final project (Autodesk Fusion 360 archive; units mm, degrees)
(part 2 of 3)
description: Part Number
part number: Ceramic
part number: Contacts
part number: Contacts (Mirror #1)
part number: Overcoat
part number: Resistor-1206
part number: SOT-223
part number: FINALALI 1.3.1
part number: FINALALI 1.3.2
part number: Header_SMD_01x02_P2.54mm_Horizontal_Male
base_feature "Base Feature1"
base_feature "Base Feature1"
base_feature "Base Feature1"
base_feature "Base Feature1"
base_feature "Base Feature1"
base_feature "Base Feature1"
base_feature "Base Feature1"
base_feature "Base Feature1"
base_feature "Base Feature1"
base_feature "Base Feature1"
base_feature "Base Feature1"
base_feature "Base Feature1"
base_feature "Base Feature1"
base_feature "Base Feature1"
base_feature "Base Feature1"
base_feature "Base Feature1"
base_feature "Base Feature1"
base_feature "Base Feature1"
base_feature "Base Feature1"
base_feature "Base Feature1"
base_feature "Base Feature1"
base_feature "Base Feature1"
base_feature "Base Feature1"
base_feature "Base Feature1"
base_feature "Base Feature1"
base_feature "Base Feature1"
base_feature "Base Feature1"
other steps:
create_component "CreateComponent1"
create_component "CreateComponent1"
create_component "CreateComponent2"
create_component "CreateComponent3"
create_component "CreateComponent4"
create_component "CreateComponent2"
create_component "CreateComponent3"
create_component "CreateComponent1"
create_component "CreateComponent2"
create_component "CreateComponent4"
create_component "CreateComponent1"
create_component "CreateComponent2"
create_component "CreateComponent3"
create_component "CreateComponent5"
create_component "CreateComponent6"
create_component "CreateComponent1"
create_component "CreateComponent2"
create_component "CreateComponent3"
create_component "CreateComponent4"
create_component "CreateComponent7"
create_component "CreateComponent1"
create_component "CreateComponent8"
create_component "CreateComponent1"
create_component "CreateComponent2"
create_component "CreateComponent9"
create_component "CreateComponent1"
create_component "CreateComponent2"
create_component "CreateComponent1"
create_component "CreateComponent2"
create_component "CreateComponent3"
create_component "CreateComponent4"
create_component "CreateComponent3"
create_component "CreateComponent4"
create_component "CreateComponent10"
create_component "CreateComponent11"

design "Enclosure" references "PCB TEST", "FINAL ALI", "FINALALI"
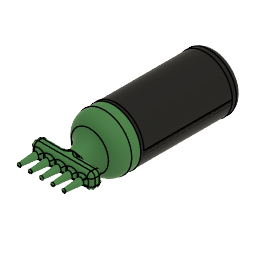
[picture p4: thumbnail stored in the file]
parameter "CLEARANCE" = 0.3
parameter "circle_1" = 54
parameter "fillet" = 10
parameter "d265" = 3
parameter "d322" = 7
sketch "Sketch1" plane through (0, 0, 0) normal (1, 0, 0) x axis (0, 1, 0)
  line L1 (-56, 12.5) -> (-56, 0)
  line L2 (-44, 12.5) -> (-56, 12.5)
  line L3 (-44, 27) -> (-44, 12.5)
  line L4 (56, 27) -> (-44, 27)
  line L5 (56, 0) -> (56, 27)
  line L6 (-56, 0) -> (56, 0)
  line L7 (46, 17) -> (46, 27)
  line L8 (56, 17) -> (46, 17)
  line L9 (-56, 12.5) -> (-44, 12.5)
  line L10 (-56, 27) -> (-56, 12.5)
  line L11 (-44, 27) -> (-56, 27)
  line L12 (-44, 12.5) -> (-44, 27)
  line L13 (55, 16.9) -> (55, 17)
  line L14 (56, 16.9) -> (55, 16.9)
  point P1 (0, 0)
  point P8 (46, 27)
  point P10 (56, 17)
  point P14 (55, 17)
  point P16 (56, 16.9)
  point P6 (56, 27)
  point P7 (56, 0)
  point P2 (-56, 0)
  point P3 (-56, 12.5)
  point P5 (-44, 27)
  point P9 (46, 17)
  point P15 (55, 16.9)
  vertical L1
  perpendicular L1 L2
  perpendicular L2 L3
  perpendicular L3 L4
  perpendicular L4 L5
  perpendicular L1 L6
  midpoint P1 L6
  coincident L4 P8
  perpendicular L4 L7
  coincident L5 P10
  perpendicular L5 L8
  horizontal L9
  vertical L10
  horizontal L11
  vertical L12
  collinear L1 L10
  collinear L4 L11
  coincident L8 P14
  perpendicular L8 L13
  coincident L5 P16
  perpendicular L5 L14
  dimension "d1" distance P6 P7 = 27
  dimension "d2" distance P2 P3 = 12.5 (= "( 25 / 2 ) * 1 mm")
  dimension "d3" distance L1 L3 = 12
  dimension "d4" distance P5 P6 = 100
  dimension "d5" distance P9 P10 = 10
  dimension "d79" distance P15 P16 = 1
  dimension "d80" distance P14 P15 = 0.1
  dimension "d173" distance P7 L8 = 17
revolve "Revolve1" sketch "Sketch1" AlongAngle 360
revolve "Revolve2" sketch "Sketch1" AlongAngle 360 bodies "back cover"
shell "Shell1" innerThickness 3
split "Split1"
split "Split2"
split "Split3" bodies "top cover"
combine "Combine2"
sketch "Sketch2" plane through (0, 46, 0) normal (0, 1, 0) x axis (-1, 0, 0)
  line L1 (-27, 0) -> (-24, 0)
  line L2 (24, 0) -> (27, 0)
  line L3 (0, -27) -> (0, 24)
  line L4 (-24.955, -1.5) -> (-25.9052, -2.2186)
  line L5 (-24.5605, -4.6669) -> (-25.658, -4.2033)
  line L6 (0, 0) -> (-26.793, -3.3369)
  line L7 (24.955, -1.5) -> (25.9052, -2.2186)
  line L8 (24.5605, -4.6669) -> (25.658, -4.2033)
  line L9 (-23.5661, -4.543) -> (-24.5605, -4.6669)
  line L10 (23.5661, -4.543) -> (24.5605, -4.6669)
  arc A1 centre (0, 0) radius 24 clockwise from (-24, 0) to (24, 0)
  arc A2 centre (0, 0) radius 27 clockwise from (27, 0) to (-27, 0)
  circle C1 centre (0, 0) radius 17
  circle C2 centre (0, 0) radius 24
  circle C3 centre (0, 0) radius 23.5
  circle C4 centre (0, 0) radius 25
  circle C5 centre (0, 0) radius 26
  point P7 (0, 24)
  point P8 (0, -27)
  point P3 (-24, 0)
  point P13 (-25.9052, -2.2186)
  point P14 (-24.955, -1.5)
  point P15 (-25.658, -4.2033)
  point P16 (-24.5605, -4.6669)
  point P17 (-26.793, -3.3369)
  point P4 (0, 0)
  point P18 (0, 0)
  point P19 (25.9052, -2.2186)
  point P20 (24.955, -1.5)
  point P21 (25.658, -4.2033)
  point P22 (24.5605, -4.6669)
  point P23 (-23.5661, -4.543)
  point P24 (24.5605, -4.6669)
  point P25 (23.5661, -4.543)
  midpoint A1 P7
  midpoint A2 P8
  concentric A1 C2
  coincident P3 C2
  concentric A1 C3
  concentric A1 C4
  concentric C4 C5
  coincident C5 P13
  coincident C4 P14
  coincident C5 P15
  coincident C4 P16
  coincident A2 P17
  coincident P4 P18
  symmetric L4 L5 L6
  symmetric L3 P13 P19
  symmetric L3 P14 P20
  symmetric L3 P15 P21
  symmetric L3 P16 P22
  coincident C2 P23
  parallel L6 L9
  symmetric L3 P16 P24
  symmetric L3 P23 P25
  dimension "d10" distance C2 C4 = 1
  dimension "d11" distance A2 C5 = 1
  dimension "d12" distance P13 P15 = 2
  dimension "d13" angle L5 L6 = 30
  dimension "d14" distance L1 P14 = 1.5
extrude "Extrude1" add sketch "Sketch2" profile of L1 L2 C2 C4 C5 L4 L5 L7 L8 L9 L10 to an object
extrude "Extrude2" add sketch "Sketch2" profile of A1 L1 L2 C2 C4 along normal blind 1.5
extrude "Extrude3" of existing geometry blind -1.5
combine "Combine3"
extrude "Extrude4" add sketch "Sketch2" profile of C2 C4 L9 L10 along normal blind 1.5
extrude "Extrude5" cut sketch "Sketch2" profile of A1 L1 L2 C2 C4 L9 L10 along normal blind 1.8
offset_faces "OffsetFaces1"
offset_faces "OffsetFaces2"
offset_faces "OffsetFaces3"
extrude "Extrude6" add sketch "Sketch2" profile of L1 L2 C2 C4 L9 L10 to an object
thread "Thread4" ThreadOffset 0 ThreadLength 10
combine "Combine4"
offset_faces "OffsetFaces12" distance -0.3
thread "Thread9" ThreadOffset 0 ThreadLength 10
sketch "Sketch10" plane through (0, -41, 0) normal (0, 1, 0) x axis (-1, 0, 0)
  line L1 (-26.2177, -2.0789) -> (-25.2636, -1.3573)
  line L2 (-24.6032, -4.9745) -> (-25.9267, -4.4154)
  line L3 (-23.5073, -4.838) -> (-24.6032, -4.9745)
  line L4 (25.1559, -4.741) -> (23.5661, -4.543)
  line L5 (25.9267, -4.4154) -> (25.1559, -4.741)
  line L6 (25.2636, -1.3573) -> (26.2177, -2.0789)
  line L7 (23.6981, -0.3) -> (25.2982, -0.3)
  line L8 (-25.2982, -0.3) -> (-23.6981, -0.3)
  line L9 (-1, 9.4472) -> (1, 9.4472)
  line L10 (-1, -9.4472) -> (-1, 9.4472)
  line L11 (1, -9.4472) -> (-1, -9.4472)
  line L12 (1, 9.4472) -> (1, -9.4472)
  line L13 (-1, -9.4472) -> (1, 9.4472)
  line L14 (1, -9.4472) -> (-1, 9.4472)
  circle C1 centre (0, 0) radius 9.5
  arc A1 centre (0, 0) radius 26.3 clockwise from (-25.9267, -4.4154) to (-26.2177, -2.0789)
  arc A2 centre (0, 0) radius 24 clockwise from (23.5661, -4.543) to (-23.5073, -4.838)
  arc A3 centre (0, 0) radius 26.3 clockwise from (26.2177, -2.0789) to (25.9267, -4.4154)
  arc A4 centre (0, 0) radius 25.3 clockwise from (25.2982, -0.3) to (25.2636, -1.3573)
  arc A5 centre (0, 0) radius 23.7 clockwise from (-23.6981, -0.3) to (23.6981, -0.3)
  arc A6 centre (0, 0) radius 25.3 clockwise from (-25.2636, -1.3573) to (-25.2982, -0.3)
  circle C2 centre (4.2, 0) radius 2.5
  circle C3 centre (4.2, 0) radius 1.25
  point P21 (0, 0)
  point P17 (1, 9.4472)
  point P2 (0, 0)
  point P19 (-1, -9.4472)
  point P20 (1, -9.4472)
  horizontal L9
  perpendicular L9 L10
  parallel L9 L11
  parallel L10 L12
  coincident L13 P21
  coincident L14 P21
  coincident C1 P17
  coincident P2 P21
  concentric C2 C3
  dimension "d106" distance P19 P20 = 2
  dimension "d111" diameter C2 = 5
  dimension "d117" diameter C3 = 2.5
extrude "Extrude14" add sketch "Sketch10" profile of C1 L9 L10 L11 L12 against normal blind 15
extrude "Extrude15" add sketch "Sketch10" profile of C1 L12 against normal blind 5
sketch "Sketch11" plane through (0, -41, 0) normal (0, 1, 0) x axis (-1, 0, 0)
  circle C1 centre (4.1977, -0.018) radius 1.25
  dimension "d114" diameter C1 = 2.5
extrude "Extrude17" cut sketch "Sketch11" against normal blind 15.8
mirror "Mirror1" mirrorStitchTolerance 0.1
sketch "Sketch12" plane through (0, -41, 0) normal (0, 1, 0) x axis (-1, 0, 0)
  line L1 (-24.6032, -4.9745) -> (-25.9267, -4.4154)
  line L2 (-23.5073, -4.838) -> (-24.6032, -4.9745)
  line L3 (25.1559, -4.741) -> (23.5661, -4.543)
  line L4 (25.9267, -4.4154) -> (25.1559, -4.741)
  line L5 (25.2636, -1.3573) -> (26.2177, -2.0789)
  line L6 (23.6981, -0.3) -> (25.2982, -0.3)
  line L7 (-25.2982, -0.3) -> (-23.6981, -0.3)
  line L8 (-26.2177, -2.0789) -> (-25.2636, -1.3573)
  circle C1 centre (4.1977, -0.018) radius 1.25
  circle C2 centre (-4.1977, -0.018) radius 1.25
  arc A1 centre (0, 0) radius 24 clockwise from (23.5661, -4.543) to (-23.5073, -4.838)
  arc A2 centre (0, 0) radius 26.3 clockwise from (26.2177, -2.0789) to (25.9267, -4.4154)
  arc A3 centre (0, 0) radius 25.3 clockwise from (25.2982, -0.3) to (25.2636, -1.3573)
  arc A4 centre (0, 0) radius 23.7 clockwise from (-23.6981, -0.3) to (23.6981, -0.3)
  arc A5 centre (0, 0) radius 25.3 clockwise from (-25.2636, -1.3573) to (-25.2982, -0.3)
  arc A6 centre (0, 0) radius 26.3 clockwise from (-25.9267, -4.4154) to (-26.2177, -2.0789)
  circle C3 centre (-4.1977, -0.018) radius 2.5
  concentric C2 C3
  dimension "d122" diameter C3 = 5
extrude "Extrude19" add sketch "Sketch12" profile of C2 C3 along normal blind 10
sketch "Sketch13" plane through (0, -41, 0) normal (0, 1, 0) x axis (-1, 0, 0)
  line L1 (-24.6032, -4.9745) -> (-25.9267, -4.4154)
  line L2 (-23.5073, -4.838) -> (-24.6032, -4.9745)
  line L3 (25.1559, -4.741) -> (23.5661, -4.543)
  line L4 (25.9267, -4.4154) -> (25.1559, -4.741)
  line L5 (25.2636, -1.3573) -> (26.2177, -2.0789)
  line L6 (23.6981, -0.3) -> (25.2982, -0.3)
  line L7 (-25.2982, -0.3) -> (-23.6981, -0.3)
  line L8 (-26.2177, -2.0789) -> (-25.2636, -1.3573)
  arc A1 centre (0, 0) radius 24 clockwise from (23.5661, -4.543) to (-23.5073, -4.838)
  arc A2 centre (0, 0) radius 26.3 clockwise from (26.2177, -2.0789) to (25.9267, -4.4154)
  arc A3 centre (0, 0) radius 25.3 clockwise from (25.2982, -0.3) to (25.2636, -1.3573)
  arc A4 centre (0, 0) radius 23.7 clockwise from (-23.6981, -0.3) to (23.6981, -0.3)
  arc A5 centre (0, 0) radius 25.3 clockwise from (-25.2636, -1.3573) to (-25.2982, -0.3)
  arc A6 centre (0, 0) radius 26.3 clockwise from (-25.9267, -4.4154) to (-26.2177, -2.0789)
  circle C1 centre (4.1977, -0.018) radius 1.25
  circle C2 centre (4.1977, -0.018) radius 2.5
  circle C3 centre (-4.1977, -0.018) radius 2.5
  concentric C1 C2
  dimension "d127" diameter C2 = 5
extrude "Extrude20" add sketch "Sketch13" profile of C1 C2 along normal blind 10
fillet "Fillet11" radius 3
sketch "Sketch14" plane through (0, 56, 0) normal (0, 1, 0) x axis (-1, 0, 0)
  line L1 (-10.15, 2.015) -> (10.15, 2.015)
  line L2 (-10.15, -2.015) -> (-10.15, 2.015)
  line L3 (10.15, -2.015) -> (-10.15, -2.015)
  line L4 (10.15, 2.015) -> (10.15, -2.015)
  line L5 (-10.15, -2.015) -> (10.15, 2.015)
  line L6 (10.15, -2.015) -> (-10.15, 2.015)
  circle C1 centre (0, 0) radius 16.9
  point P7 (0, 0)
  point P1 (0, 0)
  point P5 (-10.15, -2.015)
  point P6 (10.15, -2.015)
  point P4 (-10.15, 2.015)
  horizontal L1
  perpendicular L1 L2
  parallel L1 L3
  parallel L2 L4
  coincident L5 P7
  coincident L6 P7
  coincident P1 P7
  dimension "d134" distance P5 P6 = 20.3
  dimension "d135" distance P4 P5 = 4.03
extrude "Extrude21" cut sketch "Sketch14" profile of L1 L2 L3 L4 against normal blind 35
fillet "Fillet12" radius 2
chamfer "Chamfer4" distance 1
sketch "Sketch15" plane through (0, -44, 0) normal (0, -1, 0) x axis (1, 0, 0)
  curve K1 (4.9507, -9.5814) -> (7.7632, 9.8383)
  curve K2 (-3.6675, 11.9837) -> (-8.088, -7.1342)
  line L1 (0, 27) -> (0, 0)
  line L2 (0, -27) -> (0, 0)
  line L3 (1, -13.5) -> (-1, -13.5)
  line L4 (2, -23) -> (2, -14.5)
  line L5 (-1, -24) -> (1, -24)
  line L6 (-2, -14.5) -> (-2, -23)
  line L7 (2, -16) -> (-2, -16)
  line L8 (2, -22) -> (-2, -22)
  line L9 (1, -23) -> (-1, -23)
  line L10 (1, -14.5) -> (-1, -14.5)
  arc A1 centre (0, 0) radius 12.5324 clockwise from (-3.6675, 11.9837) to (7.7632, 9.8383)
  arc A2 centre (0, 0) radius 10.7848 clockwise from (4.9507, -9.5814) to (-8.088, -7.1342)
  circle C1 centre (0, 0) radius 27
  circle C2 centre (0, 0) radius 18
  circle C3 centre (0, 0) radius 20
  circle C4 centre (0, 0) radius 27
  circle C5 centre (0, 0) radius 16
  circle C6 centre (0, 0) radius 22
  arc A3 centre (-1, -14.5) radius 1 clockwise from (-2, -14.5) to (-1, -13.5)
  arc A4 centre (1, -14.5) radius 1 clockwise from (1, -13.5) to (2, -14.5)
  arc A5 centre (1, -23) radius 1 clockwise from (2, -23) to (1, -24)
  arc A6 centre (-1, -23) radius 1 clockwise from (-1, -24) to (-2, -23)
  circle C7 centre (0, -23) radius 0.45
  circle C8 centre (0, -14.5) radius 0.45
  point P1 (0, 0)
  point P7 (0, 0)
  point P8 (0, 0)
  point P12 (0, 0)
  point P13 (0, 27)
  point P14 (0, -27)
  point P15 (-2, -16)
  point P16 (2, -16)
  point P17 (-2, -22)
  point P18 (2, -22)
  point P30 (-1, -23)
  point P31 (-1, -23)
  point P27 (1, -23)
  point P32 (1, -23)
  point P33 (0, -23)
  point P21 (-1, -14.5)
  point P34 (-1, -14.5)
  point P24 (1, -14.5)
  point P35 (1, -14.5)
  point P36 (0, -14.5)
  coincident P1 P7
  coincident P1 P8
  concentric C2 C5
  coincident P7 P12
  coincident C4 P13
  vertical L1
  coincident C4 P14
  vertical L2
  horizontal L3
  vertical L4
  horizontal L5
  vertical L6
  symmetric L2 L4 L6
  coincident L6 P15
  coincident L4 P16
  perpendicular L4 L7
  coincident L6 P17
  coincident L4 P18
  perpendicular L4 L8
  tangent C5 L7
  tangent C6 L8
  tangent L3 A3
  tangent L6 A3
  tangent L3 A4
  tangent L4 A4
  equal A3 A4
  tangent L4 A5
  tangent L5 A5
  equal A3 A5
  tangent L5 A6
  tangent L6 A6
  equal A3 A6
  coincident P30 P31
  coincident P27 P32
  midpoint L9 P33
  coincident P21 P34
  coincident P24 P35
  midpoint L10 P36
  dimension "d151" distance C1 C6 = 5
  dimension "d152" distance C3 C6 = 2
  dimension "d153" distance C2 C3 = 2
  dimension "d154" distance C2 C5 = 2
  dimension "d176" distance L5 L8 = 2
  dimension "d177" distance L3 L7 = 2.5
  dimension "d178" distance L4 L6 = 4
  dimension "d179" radius A3 = 1
  dimension "d180" diameter C7 = 0.9
  dimension "d181" diameter C8 = 0.9
fillet "Fillet13" radius 6
chamfer "Chamfer5" distance 3
chamfer "Chamfer6" distance 3
fillet "Fillet14" radius 2
extrude "Extrude23" cut sketch "Sketch15" profile of C2 C3 C6 C5 L1 L3 L4 L5 L6 A3 A4 A5 A6 C7 C8 against normal blind 1.77 (magnitude of "-1.17 mm - 0.60 mm")
extrude "Extrude24" cut sketch "Sketch15" profile of C7 C8 against normal blind 6.7
fillet "Fillet16" radius 1
sketch "Sketch17" plane through (0, -42.23, 0) normal (0, -1, 0) x axis (1, 0, 0)
  line L1 (2, -14.5) -> (2, -14.6969)
  line L2 (-1, -13.5) -> (1, -13.5)
  line L3 (-2, -14.6969) -> (-2, -14.5)
  line L4 (-2, -23) -> (-2, -22.8035)
  line L5 (1, -24) -> (-1, -24)
  line L6 (2, -22.8035) -> (2, -23)
  circle C1 centre (0, -14.5) radius 0.45
  circle C2 centre (0, -23) radius 0.45
  arc A1 centre (1, -14.5) radius 1 clockwise from (1, -13.5) to (2, -14.5)
  arc A2 centre (-1, -14.5) radius 1 clockwise from (-2, -14.5) to (-1, -13.5)
  arc A3 centre (-3, -14.6969) radius 1 clockwise from (-2, -14.6969) to (-3.2, -15.6767)
  arc A4 centre (0, 0) radius 16 clockwise from (-3.2, -15.6767) to (3.2, -15.6767)
  arc A5 centre (3, -14.6969) radius 1 clockwise from (3.2, -15.6767) to (2, -14.6969)
  arc A6 centre (-1, -23) radius 1 clockwise from (-1, -24) to (-2, -23)
  arc A7 centre (1, -23) radius 1 clockwise from (2, -23) to (1, -24)
  arc A8 centre (3, -22.8035) radius 1 clockwise from (2, -22.8035) to (2.8696, -21.8121)
  arc A9 centre (0, 0) radius 22 clockwise from (-2.8696, -21.8121) to (2.8696, -21.8121)
  arc A10 centre (-3, -22.8035) radius 1 clockwise from (-2.8696, -21.8121) to (-2, -22.8035)
  circle C3 centre (0, 0) radius 18.1
  circle C4 centre (0, 0) radius 19.9
  concentric A4 C3
  concentric C3 C4
  dimension "d186" distance A4 C3 = 2.1
  dimension "d187" distance A9 C4 = 2.1
sketch "Sketch1" plane through (0, 0, 0) normal (0, 1, 0) x axis (1, 0, 0)
  line L1 (-20, -20) -> (20, -20)
  line L2 (-20, 20) -> (-20, -20)
  line L3 (20, 20) -> (-20, 20)
  line L4 (20, -20) -> (20, 20)
  line L5 (-20, 20) -> (20, -20)
  line L6 (20, 20) -> (-20, -20)
  point P6 (0, 0)
  point P1 (0, 0)
  point P4 (-20, 20)
  point P5 (20, 20)
  point P3 (-20, -20)
  horizontal L1
  perpendicular L1 L2
  parallel L1 L3
  parallel L2 L4
  coincident L5 P6
  coincident L6 P6
  coincident P1 P6
  dimension "d1_2" distance P4 P5 = 40
  dimension "d2_2" distance P3 P4 = 40
extrude "Extrude1" new body sketch "Sketch1" profile of L1 L2 L3 L4 distance 6 named "d3_2"
sketch "Sketch2" plane through (0, 0, 20) normal (0, 0, 1) x axis (-1, 0, 0)
  line L1 (-20, -6) -> (-20, 6)
  line L2 (20, -6) -> (-20, -6)
  line L3 (20, 6) -> (20, -6)
  line L4 (-20, 6) -> (20, 6)
  circle C1 centre (15, 0) radius 3.8143
  circle C2 centre (-15, 0) radius 3.6582
extrude "Extrude2" add sketch "Sketch2" profile of C1 C2 along normal blind 12 named "d5_2"
chamfer "Chamfer1" distance 1.5 named "d7_2"
component_insert "Component Insert20"
position "Position18"
sketch "Sketch33" plane through (0, 0, 0) normal (0, 1, 0) x axis (1, 0, 0)
  line L1 (25.9052, 2.2186) -> (24.955, 1.5)
  line L2 (24.5605, 4.6669) -> (25.658, 4.2033)
  line L3 (23.5661, 4.543) -> (24.5605, 4.6669)
  line L4 (-24.5605, 4.6669) -> (-23.5661, 4.543)
  line L5 (-25.658, 4.2033) -> (-24.5605, 4.6669)
  line L6 (-24.955, 1.5) -> (-25.9052, 2.2186)
  line L7 (-27, 0) -> (-25, 0)
  line L8 (25, 0) -> (27, 0)
  line L9 (26.9983, 0.3) -> (25.2982, 0.3)
  line L10 (-25.3, 0) -> (-27, 0)
  line L11 (-26.2177, 2.0789) -> (-25.2636, 1.3573)
  line L12 (-25.1559, 4.741) -> (-25.9267, 4.4154)
  line L13 (-23.5661, 4.543) -> (-25.1559, 4.741)
  line L14 (24.6032, 4.9745) -> (23.5073, 4.838)
  line L15 (25.9267, 4.4154) -> (24.6032, 4.9745)
  line L16 (25.2636, 1.3573) -> (26.2177, 2.0789)
  line L17 (-19.712, -51.4636) -> (-19.712, -39.4636)
  line L18 (20.288, -51.4636) -> (-19.712, -51.4636)
  line L19 (20.288, -39.4636) -> (20.288, -51.4636)
  line L20 (-19.712, -39.4636) -> (20.288, -39.4636)
  line L21 (-20, -8.4124) -> (20, -8.4124)
  line L22 (-20, 3.5876) -> (-20, -8.4124)
  line L23 (20, 3.5876) -> (-20, 3.5876)
  line L24 (20, -8.4124) -> (20, 3.5876)
  line L25 (10.6, -13.6124) -> (10.6, -8.4124)
  line L26 (-10.6, -13.6124) -> (10.6, -13.6124)
  line L27 (-10.6, -8.4124) -> (-10.6, -13.6124)
  line L28 (0, 3.5876) -> (0, -13.6124)
  line L29 (10.6, -13.6124) -> (20, -8.4124)
  line L30 (-20, -8.4124) -> (-10.6, -13.6124)
  line L31 (-22, -9.5917) -> (-11.1163, -15.6124)
  line L32 (-22, 5.5876) -> (-22, -9.5917)
  line L33 (22, 5.5876) -> (-22, 5.5876)
  line L34 (22, -9.5917) -> (22, 5.5876)
  line L35 (11.1163, -15.6124) -> (22, -9.5917)
  line L36 (-11.1163, -15.6124) -> (11.1163, -15.6124)
  line L37 (-12.5, 14.4878) -> (12.5, 14.4878)
  line L38 (-12.5, 20.4878) -> (-12.5, 14.4878)
  line L39 (12.5, 20.4878) -> (-12.5, 20.4878)
  line L40 (12.5, 14.4878) -> (12.5, 20.4878)
  line L41 (-22.9905, 5.5876) -> (22.9905, 5.5876)
  line L42 (-22.9905, 6.8876) -> (-22.9905, 5.5876)
  line L43 (22.9905, 6.8876) -> (-22.9905, 6.8876)
  line L44 (22.9905, 5.5876) -> (22.9905, 6.8876)
  line L45 (-21.3009, 9.8876) -> (21.3009, 9.8876)
  line L46 (-21.3009, 11.0576) -> (-21.3009, 9.8876)
  line L47 (21.3009, 11.0576) -> (-21.3009, 11.0576)
  line L48 (21.3009, 9.8876) -> (21.3009, 11.0576)
  line L49 (-45.7995, 19.3474) -> (-45.0495, 15.8474)
  line L50 (-51.2995, 19.3474) -> (-45.7995, 19.3474)
  line L51 (-52.6495, 15.5674) -> (-51.2995, 19.3474)
  line L52 (-52.6495, 9.4474) -> (-52.6495, 15.5674)
  line L53 (-51.5245, 9.4474) -> (-52.6495, 9.4474)
  line L54 (-51.5245, 15.8474) -> (-51.5245, 9.4474)
  line L55 (-50.8245, 15.8474) -> (-51.5245, 15.8474)
  line L56 (-50.8245, 9.4474) -> (-50.8245, 15.8474)
  line L57 (-45.0495, 9.4474) -> (-50.8245, 9.4474)
  line L58 (-45.0495, 15.8474) -> (-45.0495, 9.4474)
  line L59 (-60.257, 19.3474) -> (-54.757, 19.3474)
  line L60 (-61.007, 15.8474) -> (-60.257, 19.3474)
  line L61 (-61.007, 9.4474) -> (-61.007, 15.8474)
  line L62 (-55.232, 9.4474) -> (-61.007, 9.4474)
  line L63 (-55.232, 15.8474) -> (-55.232, 9.4474)
  line L64 (-54.532, 15.8474) -> (-55.232, 15.8474)
  line L65 (-54.532, 9.4474) -> (-54.532, 15.8474)
  line L66 (-53.407, 9.4474) -> (-54.532, 9.4474)
  line L67 (-53.407, 15.5674) -> (-53.407, 9.4474)
  line L68 (-54.757, 19.3474) -> (-53.407, 15.5674)
  line L69 (8.25, 21.0576) -> (8.25, 11.0576)
  line L70 (-8.25, 21.0576) -> (8.25, 21.0576)
  line L71 (-8.25, 11.0576) -> (-8.25, 21.0576)
  line L72 (21.7009, 10.2503) -> (21.7009, 6.8876)
  line L73 (-21.7009, 10.2503) -> (-21.7009, 6.8876)
  line L74 (20.3009, 12.8012) -> (20.3009, 11.0576)
  line L75 (-20.3009, 12.8012) -> (-20.3009, 11.0576)
  arc A1 centre (0, 0) radius 25 clockwise from (24.955, 1.5) to (25, 0)
  arc A2 centre (0, 0) radius 26 clockwise from (25.658, 4.2033) to (25.9052, 2.2186)
  arc A3 centre (0, 0) radius 24 between (-23.5661, 4.543) and (23.5661, 4.543)
  arc A4 centre (0, 0) radius 26 clockwise from (-25.9052, 2.2186) to (-25.658, 4.2033)
  arc A5 centre (0, 0) radius 25 clockwise from (-25, 0) to (-24.955, 1.5)
  arc A6 centre (0, 0) radius 27 clockwise from (27, 0) to (-27, 0)
  arc A7 centre (0, 0) radius 25.3 between (25.2982, 0.3) and (25.2636, 1.3573)
  arc A8 centre (0, 0) radius 27 clockwise from (-27, 0) to (26.9983, 0.3)
  arc A9 centre (0, 0) radius 25.3 between (-25.2636, 1.3573) and (-25.3, 0)
  arc A10 centre (0, 0) radius 26.3 between (-25.9267, 4.4154) and (-26.2177, 2.0789)
  arc A11 centre (0, 0) radius 24 between (23.5073, 4.838) and (-23.5661, 4.543)
  arc A12 centre (0, 0) radius 26.3 between (26.2177, 2.0789) and (25.9267, 4.4154)
  point P40 (10.6, -8.4124)
  point P43 (-10.6, -8.4124)
  point P44 (0, -13.6124)
  point P45 (0, 3.5876)
  point P50 (22, -9.5917)
  point P47 (-22, -9.5917)
  point P54 (-12.5, 20.4878)
  point P55 (12.5, 20.4878)
  point P59 (22.9905, 6.8876)
  point P58 (-22.9905, 6.8876)
  point P63 (21.3009, 11.0576)
  point P62 (-21.3009, 11.0576)
  point P49 (22, 5.5876)
  point P84 (8.25, 11.0576)
  point P87 (-8.25, 11.0576)
  point P88 (21.7009, 6.8876)
  point P89 (21.7009, 10.2503)
  point P90 (-21.7009, 6.8876)
  point P91 (-21.7009, 10.2503)
  point P92 (20.3009, 11.0576)
  point P93 (20.3009, 12.8012)
  point P94 (-20.3009, 11.0576)
  point P95 (-20.3009, 12.8012)
  point P33 (-19.712, -51.4636)
  point P34 (20.288, -51.4636)
  point P35 (20.288, -39.4636)
  point P36 (20, -8.4124)
  point P37 (-20, -8.4124)
  point P39 (20, 3.5876)
  point P41 (10.6, -13.6124)
  point P42 (-10.6, -13.6124)
  point P52 (12.5, 14.4878)
  point P53 (-12.5, 14.4878)
  point P85 (8.25, 21.0576)
  point P86 (-8.25, 21.0576)
  horizontal L21
  vertical L22
  horizontal L23
  vertical L24
  coincident L21 P40
  perpendicular L21 L25
  perpendicular L25 L26
  coincident L21 P43
  perpendicular L21 L27
  midpoint L26 P44
  coincident L23 P45
  perpendicular L23 L28
  midpoint L23 P45
  coincident A3 P50
  coincident A3 P47
  horizontal L37
  vertical L38
  horizontal L39
  vertical L40
  coincident A11 P54
  coincident A11 P55
  horizontal L41
  vertical L42
  horizontal L43
  vertical L44
  coincident A11 P59
  coincident A11 P58
  horizontal L45
  vertical L46
  horizontal L47
  vertical L48
  coincident A11 P63
  coincident A11 P62
  coincident P49 L41
  coincident L47 P84
  perpendicular L47 L69
  perpendicular L69 L70
  coincident L47 P87
  perpendicular L47 L71
  symmetric L28 L69 L71
  coincident L43 P88
  coincident A11 P89
  perpendicular L43 L72
  coincident L43 P90
  coincident A11 P91
  perpendicular L43 L73
  coincident L47 P92
  coincident A11 P93
  perpendicular L47 L74
  coincident L47 P94
  coincident A11 P95
  perpendicular L47 L75
  dimension "d254" distance P33 P34 = 40
  dimension "d255" distance P34 P35 = 12
  dimension "d256" distance P36 P37 = 40
  dimension "d257" distance P36 P39 = 12
  dimension "d258" distance P40 P41 = 5.2
  dimension "d259" distance P41 P42 = 21.2
  dimension "d260" = -2
  dimension "d261" distance P52 P53 = 25
  dimension "d262" distance P52 P55 = 6
  dimension "d263" distance L41 L43 = 1.3
  dimension "d264" distance L45 L47 = 1.17
  dimension "d265" distance L43 L45 = 3
  dimension "d266" distance P85 P86 = 16.5
  dimension "d267" distance P86 P87 = 10
  dimension "d268" distance L46 L73 = 0.4
  dimension "d269" distance L48 L72 = 0.4 (= "d268")
  dimension "d274" distance L46 L75 = 1
  dimension "d275" distance L48 L74 = 1 (= "d274")
extrude "Extrude40" add sketch "Sketch33" profile of A11 L43 L47 L72 L73 L74 L75 to an object Side2Offset 0
extrude "Extrude41" add sketch "Sketch33" profile of A11 L39 L69 L70 L71 to an object from offset 7
sketch "Sketch1" plane through (0, 0, -11.0576) normal (0, 0, 1) x axis (-1, 0, 0)
  curve K1 (-21.3009, -41) -> (-20.3009, -42.659)
  line L1 (-20.3009, 40.659) -> (-20.3009, -42.659)
  curve K2 (-20.3009, 40.659) -> (-21.3009, 39)
  line L2 (-21.3009, -41) -> (-21.3009, 39)
  curve K3 (20.3009, -42.659) -> (21.3009, -41)
  line L3 (21.3009, 39) -> (21.3009, -41)
  curve K4 (21.3009, 39) -> (20.3009, 40.659)
  line L4 (20.3009, -42.659) -> (20.3009, 40.659)
  line L5 (-21.3009, 38.659) -> (21.3009, 38.659)
  line L6 (21.3009, -21.341) -> (-21.3009, -21.341)
  line L7 (0, 38.659) -> (0, -21.341)
  line L8 (21.3009, 8.659) -> (-21.3009, 8.659)
  circle C1 centre (-18.8009, -18.841) radius 1
  circle C2 centre (-18.8009, -18.841) radius 2.5
  circle C3 centre (-18.8009, 36.159) radius 1
  circle C4 centre (-18.8009, 36.159) radius 2.5
  circle C5 centre (18.8009, -18.841) radius 1
  circle C6 centre (18.8009, -18.841) radius 2.5
  circle C7 centre (18.8009, 36.159) radius 1
  circle C8 centre (18.8009, 36.159) radius 2.5
  point P10 (21.3009, 38.659)
  point P11 (-21.3009, 38.659)
  point P12 (-21.3009, -21.341)
  point P13 (21.3009, -21.341)
  point P14 (0, -21.341)
  point P15 (0, 38.659)
  point P16 (-21.3009, 8.659)
  point P17 (21.3009, 8.659)
  point P9 (20.3009, 40.659)
  coincident L3 P10
  coincident L2 P11
  perpendicular L2 L5
  coincident L2 P12
  coincident L3 P13
  perpendicular L3 L6
  midpoint L6 P14
  midpoint L5 P15
  coincident L2 P16
  coincident L3 P17
  perpendicular L3 L8
  midpoint L7 L8
  concentric C1 C2
  tangent L2 C2
  tangent L6 C2
  symmetric L8 C1 C3
  symmetric L8 C2 C4
  symmetric L7 C1 C5
  symmetric L7 C2 C6
  symmetric L7 C3 C7
  symmetric L7 C4 C8
  dimension "d279" distance P9 L5 = 2
  dimension "d280" distance L5 L6 = 60
  dimension "d285" diameter C1 = 2
  dimension "d286" distance C1 C2 = 1.5
extrude "Extrude1" new body sketch "Sketch1" profile of L1 L2 L3 L4 L5 L6 C1 C2 C3 C4 C5 C6 C7 C8 along normal blind 1.17
extrude "Extrude44" add sketch "Sketch1" profile of L1 L4 C1 C2 C3 C4 C5 C6 C7 C8 to an object
offset_faces "OffsetFaces18" distance 0.3
offset_faces "OffsetFaces19" distance -2
position "Position19"
sketch "Sketch1" plane through (0, 0, -6.8876) normal (0, 0, 1) x axis (-1, 0, 0)
  curve K1 (21.7009, -42.8468) -> (22.9905, -41)
  line L1 (22.9905, 39) -> (22.9905, -41)
  curve K2 (22.9905, 39) -> (21.7009, 40.8468)
  line L2 (21.7009, -42.8468) -> (21.7009, 40.8468)
  curve K3 (-22.9905, -41) -> (-21.7009, -42.8468)
  line L3 (-21.7009, 40.8468) -> (-21.7009, -42.8468)
  curve K4 (-21.7009, 40.8468) -> (-22.9905, 39)
  line L4 (-22.9905, -41) -> (-22.9905, 39)
  line L5 (22.9905, 1) -> (-22.9905, 1)
  line L6 (22.9905, -41) -> (-22.9905, -41)
  point P10 (-22.9905, 1)
  point P11 (22.9905, 1)
  point P7 (-22.9905, -41)
  point P12 (-22.9905, -41)
  point P2 (22.9905, -41)
  point P13 (22.9905, -41)
  coincident L4 P10
  coincident L1 P11
  perpendicular L1 L5
  coincident P7 P12
  coincident P2 P13
  dimension "d293" distance L5 L6 = 42
extrude "Extrude1" new body sketch "Sketch1" profile of L1 L2 L3 L4 L5 L6 along normal blind 1.7
extrude "Extrude45" cut of existing geometry blind -0.5
sketch "Sketch2" plane through (0, 0, -9.8876) normal (0, 0, 1) x axis (-1, 0, 0)
  line L1 (-18.8009, 38.659) -> (18.8009, 38.659)
  line L2 (-21.3009, -18.841) -> (-21.3009, 36.159)
  line L3 (18.8009, -21.341) -> (-18.8009, -21.341)
  line L4 (21.3009, 36.159) -> (21.3009, -18.841)
  circle C1 centre (18.8009, 36.159) radius 1
  circle C2 centre (18.8009, -18.841) radius 1
  circle C3 centre (-18.8009, -18.841) radius 1
  circle C4 centre (-18.8009, 36.159) radius 1
  arc A1 centre (18.8009, 36.159) radius 2.5 clockwise from (18.8009, 38.659) to (21.3009, 36.159)
  arc A2 centre (-18.8009, 36.159) radius 2.5 clockwise from (-21.3009, 36.159) to (-18.8009, 38.659)
  arc A3 centre (-18.8009, -18.841) radius 2.5 clockwise from (-18.8009, -21.341) to (-21.3009, -18.841)
  arc A4 centre (18.8009, -18.841) radius 2.5 clockwise from (21.3009, -18.841) to (18.8009, -21.341)
fillet "Fillet20" radius 1
sketch "Sketch37" plane through (0, -42.5, 0) normal (0, -1, 0) x axis (1, 0, 0)
  line L1 (-24, 0) -> (-25, 0)
  line L2 (25, 0) -> (24, 0)
  line L3 (-22, 9.5917) -> (-11.1163, 15.6124)
  line L4 (-11.1163, 15.6124) -> (11.1163, 15.6124)
  line L5 (11.1163, 15.6124) -> (22, 9.5917)
  line L6 (22, 9.5917) -> (22, -5.5876)
  line L7 (-22, -5.5876) -> (-22, 9.5917)
  arc A1 centre (0, 0) radius 25 clockwise from (-25, 0) to (25, 0)
  arc A2 centre (0, 0) radius 24 clockwise from (-24, 0) to (24, 0)
extrude "Extrude46" add sketch "Sketch37" profile of A2 L3 L4 L5 blind -50 from offset -25
sketch "Sketch1" plane through (0, 0, 0) normal (0, 0, 1) x axis (1, 0, 0)
  circle C1 centre (0, 0) radius 27
  point P1 (0, 0)
  point P2 (0, 0)
  coincident P1 P2
  dimension "d3_1" diameter C1 = 54 (= "circle_1")
extrude "Extrude1" new body sketch "Sketch1" along normal blind 25 named "d4_1"
fillet "Fillet1" radius 16 named "d7_1"
sketch "Sketch2" plane through (0, 0, 25) normal (0, 0, 1) x axis (-1, 0, 0)
  circle C1 centre (0, 0) radius 11
  circle C2 centre (0, 0) radius 7.5
  point P1 (0, 0)
  point P3 (0, 0)
  coincident P1 P3
  dimension "d8_1" diameter C2 = 15
extrude "Extrude2" add sketch "Sketch2" profile of C2 along normal blind 15 named "d9_1"
fillet "Fillet2" radius 20 named "d12_1"
sketch "Sketch3" plane through (0, 0, 40) normal (0, 0, 1) x axis (-1, 0, 0)
  line L1 (30, -7.5) -> (-30, -7.5)
  line L2 (30, 7.5) -> (30, -7.5)
  line L3 (-30, 7.5) -> (30, 7.5)
  line L4 (-30, -7.5) -> (-30, 7.5)
  line L5 (30, 7.5) -> (-30, -7.5)
  line L6 (-30, 7.5) -> (30, -7.5)
  circle C1 centre (0, 0) radius 7.5
  point P6 (0, 0)
  point P1 (0, 0)
  point P4 (30, 7.5)
  point P5 (-30, 7.5)
  point P3 (30, -7.5)
  horizontal L1
  perpendicular L1 L2
  parallel L1 L3
  parallel L2 L4
  coincident L5 P6
  coincident L6 P6
  coincident P1 P6
  dimension "d13_1" distance P4 P5 = 60
  dimension "d14_1" distance P3 P4 = 15
extrude "Extrude3" add sketch "Sketch3" profile of L1 L2 L3 L4 along normal blind 12 named "d15_1"
fillet "Fillet3" radius 5 named "d18_1"
fillet "Fillet4" radius 4 named "d20_1"
sketch "Sketch4" plane through (0, 0, 52) normal (0, 0, 1) x axis (-1, 0, 0)
  line L1 (26, -3.5) -> (-26, -3.5)
  line L2 (26, 3.5) -> (26, -3.5)
  line L3 (-26, 3.5) -> (26, 3.5)
  line L4 (-26, -3.5) -> (-26, 3.5)
  circle C1 centre (0, 0) radius 3.5
  circle C2 centre (-22, 0) radius 3.5
  circle C3 centre (-11, 0) radius 3.5
  circle C4 centre (11, 0) radius 3.5
  circle C5 centre (22, 0) radius 3.5
  point P1 (0, 0)
  point P6 (0, 0)
  coincident P1 P6
  tangent L3 C1
  dimension "d23_1" R-Pattern1-uDistance = 22
  dimension "d24_1" R-Pattern1-vDistance = 0
extrude "Extrude4" add sketch "Sketch4" profile of C1 C2 C3 C4 C5 along normal blind 20 named "d25_1" taper -5
fillet "Fillet5" radius 3 named "d28_1"
work_plane "WorkPlane1" AlongDistance 0 named "d29_1"
sketch "Sketch5" plane through (0, 0, 72) normal (0, 0, 1) x axis (1, 0, 0)
  circle C1 centre (22, 0) radius 0.5
  circle C2 centre (11, 0) radius 0.5
  circle C3 centre (0, 0) radius 0.5
  circle C4 centre (-11, 0) radius 0.5
  circle C5 centre (-22, 0) radius 0.5
  point P1 (0, 0)
  point P4 (0, 0)
  coincident P1 P4
  dimension "d30" diameter C1 = 1
  dimension "d31" diameter C2 = 1
  dimension "d32" diameter C3 = 1
  dimension "d33" diameter C4 = 1
  dimension "d34" diameter C5 = 1
extrude "Extrude5" cut sketch "Sketch5" against normal blind 24 named "d35_1" taper 4 named "d36_1"
sketch "Sketch6" plane through (0, 0, 0) normal (0, 1, 0) x axis (1, 0, 0)
  line L1 (-24, -48) -> (24, -48)
  horizontal L1
pipe "Pipe1" SectionSize 5 SectionThickness 1.25
fillet "Fillet6" radius 5
fillet "Fillet7" radius 1.4
sketch "Sketch7" plane through (0, 0, 0) normal (0, 1, 0) x axis (1, 0, 0)
  line L1 (0, -15) -> (0, -46)
  point P1 (0, 0)
  point P2 (0, -15)
  dimension "d45" distance P1 P2 = 15
pipe "Pipe2" SectionSize 7 SectionThickness 1.75
fillet "Fillet8" radius 5
sketch "Sketch8" plane through (0, 0, 40) normal (0, 0, -1) x axis (1, 0, 0)
  line L1 (6.6332, 3.5) -> (26, 3.5)
  line L2 (26, -3.5) -> (6.6332, -3.5)
  line L3 (26, 3.5) -> (26, -3.5)
  line L4 (0, -20) -> (0, -2.5)
  circle C1 centre (20, 0) radius 5.05
  circle C2 centre (-20, 0) radius 5.05
  arc A1 centre (0, 0) radius 7.5 clockwise from (6.6332, 3.5) to (6.6332, -3.5)
  symmetric C1 L4 C2
  dimension "d52" diameter C1 = 10.1
extrude "Extrude6" cut sketch "Sketch8" profile of L1 L2 C1 C2 against normal blind 4
sketch "Sketch9" plane through (0, 0, 0) normal (0, 1, 0) x axis (1, 0, 0)
fillet "Fillet9" radius 1
sketch "Sketch10" plane through (0, 0, 0) normal (0, 1, 0) x axis (1, 0, 0)
  curve K1 (19, 0) -> (14.95, -42)
  curve K2 (23.862, -70.7224) -> (22.5, -72)
  line L1 (25.2939, -54.356) -> (23.862, -70.7224)
  curve K3 (27.3043, -51.7814) -> (25.2939, -54.356)
  line L2 (30, -44) -> (30, -48)
  line L3 (25.05, -40) -> (26, -40)
  line L4 (25.05, -44) -> (25.05, -40)
  line L5 (14.95, -44) -> (25.05, -44)
  line L6 (14.95, -40) -> (14.95, -44)
  line L7 (7.5, -40) -> (14.95, -40)
  curve K4 (18.322, -23.2263) -> (7.5, -40)
  line L8 (27, 0) -> (27, -9)
  line L9 (-27, 0) -> (27, 0)
  line L10 (-27, -9) -> (-27, 0)
  curve K5 (-7.5, -40) -> (-18.322, -23.2263)
  line L11 (-14.95, -40) -> (-7.5, -40)
  line L12 (-14.95, -44) -> (-14.95, -40)
  line L13 (-25.05, -44) -> (-14.95, -44)
  line L14 (-25.05, -40) -> (-25.05, -44)
  line L15 (-26, -40) -> (-25.05, -40)
  line L16 (-30, -48) -> (-30, -44)
  curve K6 (-25.2939, -54.356) -> (-27.3043, -51.7814)
  line L17 (-23.862, -70.7224) -> (-25.2939, -54.356)
  curve K7 (-22.5, -72) -> (-23.862, -70.7224)
  line L18 (-23.6782, -55.1512) -> (-22.5, -72)
  curve K8 (-23.8968, -53.9983) -> (-23.6782, -55.1512)
  curve K9 (-24, -53.4607) -> (-23.8968, -53.9983)
  line L19 (-24, -50.549) -> (-24, -53.4607)
  line L20 (-24.1782, -48) -> (-24, -50.549)
  line L21 (-24, -48) -> (-24.1782, -48)
  line L22 (-24, -46.5) -> (-24, -48)
  line L23 (-8.5, -45.5) -> (-23, -45.5)
  curve K10 (-3.5, -40.5) -> (-8.5, -45.5)
  line L24 (-3.5, -15) -> (-3.5, -40.5)
  line L25 (3.5, -15) -> (-3.5, -15)
  line L26 (3.5, -40.5) -> (3.5, -15)
  curve K11 (8.5, -45.5) -> (3.5, -40.5)
  line L27 (23, -45.5) -> (8.5, -45.5)
  line L28 (24, -48) -> (24, -46.5)
  line L29 (24.1782, -48) -> (24, -48)
  line L30 (24, -50.549) -> (24.1782, -48)
  line L31 (24, -53.4607) -> (24, -50.549)
  curve K12 (23.8968, -53.9983) -> (24, -53.4607)
  curve K13 (23.6782, -55.1512) -> (23.8968, -53.9983)
  line L32 (22.5, -72) -> (23.6782, -55.1512)
  curve K14 (-20.3218, -55.1512) -> (-16.5, -50.6379)
  line L33 (-21.5, -72) -> (-20.3218, -55.1512)
  curve K15 (-20.138, -70.7224) -> (-21.5, -72)
  line L34 (-18.7396, -54.7385) -> (-20.138, -70.7224)
  line L35 (-12.862, -70.7224) -> (-14.2604, -54.7385)
  curve K16 (-11.5, -72) -> (-12.862, -70.7224)
  line L36 (-12.6782, -55.1512) -> (-11.5, -72)
  curve K17 (-16.5, -50.6379) -> (-12.6782, -55.1512)
  curve K18 (-9.3218, -55.1512) -> (-5.5, -50.6379)
  line L37 (-10.5, -72) -> (-9.3218, -55.1512)
  curve K19 (-9.138, -70.7224) -> (-10.5, -72)
  line L38 (-7.7396, -54.7385) -> (-9.138, -70.7224)
  line L39 (-1.862, -70.7224) -> (-3.2604, -54.7385)
  line L40 (-1.6782, -55.1512) -> (-0.5, -72)
  curve K20 (-5.5, -50.6379) -> (-1.6782, -55.1512)
  curve K21 (1.6782, -55.1512) -> (5.5, -50.6379)
  line L41 (0.5, -72) -> (1.6782, -55.1512)
  line L42 (3.2604, -54.7385) -> (1.862, -70.7224)
  line L43 (9.138, -70.7224) -> (7.7396, -54.7385)
  curve K22 (10.5, -72) -> (9.138, -70.7224)
  line L44 (9.3218, -55.1512) -> (10.5, -72)
  curve K23 (5.5, -50.6379) -> (9.3218, -55.1512)
  curve K24 (12.6782, -55.1512) -> (16.5, -50.6379)
  line L45 (11.5, -72) -> (12.6782, -55.1512)
  curve K25 (12.862, -70.7224) -> (11.5, -72)
  line L46 (14.2604, -54.7385) -> (12.862, -70.7224)
  line L47 (20.138, -70.7224) -> (18.7396, -54.7385)
  curve K26 (21.5, -72) -> (20.138, -70.7224)
  line L48 (20.3218, -55.1512) -> (21.5, -72)
  curve K27 (16.5, -50.6379) -> (20.3218, -55.1512)
  arc A1 centre (26, -48) radius 4 clockwise from (30, -48) to (27.3043, -51.7814)
  arc A2 centre (26, -44) radius 4 clockwise from (26, -40) to (30, -44)
  arc A3 centre (11, -9) radius 16 clockwise from (27, -9) to (18.322, -23.2263)
  arc A4 centre (-11, -9) radius 16 clockwise from (-18.322, -23.2263) to (-27, -9)
  arc A5 centre (-26, -44) radius 4 clockwise from (-30, -44) to (-26, -40)
  arc A6 centre (-26, -48) radius 4 clockwise from (-27.3043, -51.7814) to (-30, -48)
  arc A7 centre (-23, -46.5) radius 1 between (-23, -45.5) and (-24, -46.5)
  arc A8 centre (23, -46.5) radius 1 between (24, -46.5) and (23, -45.5)
  arc A9 centre (-15.751, -55) radius 3 between (-16.5, -52.095) and (-18.7396, -54.7385)
  arc A10 centre (-17.249, -55) radius 3 between (-14.2604, -54.7385) and (-16.5, -52.095)
  arc A11 centre (-4.751, -55) radius 3 between (-5.5, -52.095) and (-7.7396, -54.7385)
  arc A12 centre (-6.249, -55) radius 3 between (-3.2604, -54.7385) and (-5.5, -52.095)
  arc A13 centre (-0.4673, -70.6004) radius 1.4 clockwise from (-0.5, -72) to (-1.862, -70.7224)
  arc A14 centre (0.4673, -70.6004) radius 1.4 clockwise from (1.862, -70.7224) to (0.5, -72)
  arc A15 centre (6.249, -55) radius 3 between (5.5, -52.095) and (3.2604, -54.7385)
  arc A16 centre (4.751, -55) radius 3 between (7.7396, -54.7385) and (5.5, -52.095)
  arc A17 centre (17.249, -55) radius 3 between (16.5, -52.095) and (14.2604, -54.7385)
  arc A18 centre (15.751, -55) radius 3 between (18.7396, -54.7385) and (16.5, -52.095)
  point P2 (14.95, -42)
  coincident P2 L6
  midpoint P2 L6
pipe "Pipe3" SectionSize 2.2 SectionThickness 0.55 named "d60_1"
mirror "Mirror1" mirrorStitchTolerance 0.1
position "Position20"
fillet "Fillet10" radius 2
combine "Combine1"
split "Split1"
remove_body "RemoveBody1"
remove_body "RemoveBody2"
combine "Combine2"
offset_faces "OffsetFaces1" distance -0.2
offset_faces "OffsetFaces20" distance -0.2
offset_faces "OffsetFaces21" distance -0.5
sketch "Sketch38" plane through (0, -44, 0) normal (0, 1, 0) x axis (-1, 0, 0)
  curve K1 (6.3745, -8.9461) -> (6.3901, 11.0127)
  curve K2 (-9.9484, 7.9462) -> (-2.6969, -10.6486)
  line L1 (13.9993, 3) -> (23.9993, 3)
  line L2 (13.9993, -3) -> (13.9993, 3)
  line L3 (23.9993, -3) -> (13.9993, -3)
  line L4 (23.9993, 3) -> (23.9993, -3)
  line L5 (13.9993, -3) -> (23.9993, 3)
  line L6 (23.9993, -3) -> (13.9993, 3)
  line L7 (-23.9993, 3) -> (-13.9993, 3)
  line L8 (-23.9993, -3) -> (-23.9993, 3)
  line L9 (-13.9993, -3) -> (-23.9993, -3)
  line L10 (-13.9993, 3) -> (-13.9993, -3)
  line L11 (-23.9993, -3) -> (-13.9993, 3)
  line L12 (-13.9993, -3) -> (-23.9993, 3)
  line L13 (19.9, 0) -> (22, 0)
  line L14 (16, 0) -> (18.1, 0)
  line L15 (0, 0) -> (0, 22)
  line L16 (0, 0) -> (0, 22)
  line L17 (14.9993, 2) -> (22.9993, 2)
  line L18 (14.9993, -2) -> (14.9993, 2)
  line L19 (22.9993, -2) -> (14.9993, -2)
  line L20 (22.9993, 2) -> (22.9993, -2)
  line L21 (-22.9993, 2) -> (-14.9993, 2)
  line L22 (-22.9993, -2) -> (-22.9993, 2)
  line L23 (-14.9993, -2) -> (-22.9993, -2)
  line L24 (-14.9993, 2) -> (-14.9993, -2)
  circle C1 centre (0, 0) radius 27
  arc A1 centre (0, 0) radius 12.7324 clockwise from (-9.9484, 7.9462) to (6.3901, 11.0127)
  arc A2 centre (0, 0) radius 10.9848 clockwise from (6.3745, -8.9461) to (-2.6969, -10.6486)
  closed curve K3 centre (18.9993, 0)
  closed curve K4 centre (-18.9993, 0)
  circle C2 centre (20.95, 0) radius 0.3
  circle C3 centre (17.05, 0) radius 0.3
  circle C4 centre (20.95, 0) radius 0.95
  circle C5 centre (17.05, 0) radius 0.95
  circle C6 centre (0, 0) radius 19.9
  arc A3 centre (0, 0) radius 22 clockwise from (-2.8696, -21.8121) to (2.8696, -21.8121)
  circle C7 centre (0, 0) radius 18.1
  arc A4 centre (0, 0) radius 16 clockwise from (-3.2, -15.6767) to (3.2, -15.6767)
  circle C8 centre (-17.05, 0) radius 0.3
  circle C9 centre (-17.05, 0) radius 0.95
  circle C10 centre (-20.95, 0) radius 0.3
  circle C11 centre (-20.95, 0) radius 0.95
  point P11 (18.9993, 0)
  point P16 (-18.9993, 0)
  point P17 (18.9993, 0)
  point P18 (-18.9993, 0)
  point P19 (20.95, 0)
  point P23 (22, 0)
  point P24 (19.9, 0)
  point P33 (18.1, 0)
  point P34 (16, 0)
  point P22 (17.05, 0)
  point P35 (0, 22)
  point P25 (0, 0)
  point P36 (0, 0)
  point P37 (0, 22)
  point P38 (0, 0)
  point P9 (13.9993, -3)
  point P10 (23.9993, -3)
  point P8 (13.9993, 3)
  point P14 (-23.9993, -3)
  point P15 (-13.9993, -3)
  point P13 (-23.9993, 3)
  horizontal L1
  perpendicular L1 L2
  parallel L1 L3
  parallel L2 L4
  coincident L5 P11
  coincident L6 P11
  horizontal L7
  perpendicular L7 L8
  parallel L7 L9
  parallel L8 L10
  coincident L11 P16
  coincident L12 P16
  coincident P11 P17
  coincident P16 P18
  concentric C2 C4
  concentric C3 C5
  horizontal L13
  midpoint P19 L13
  coincident P23 A3
  coincident P24 C6
  coincident P11 L13
  coincident C7 P33
  coincident A4 P34
  horizontal L14
  coincident P11 L14
  midpoint P22 L14
  midpoint A3 P35
  coincident P25 P36
  symmetric C2 L15 C10
  symmetric C3 L15 C8
  symmetric C4 L15 C11
  symmetric C5 L15 C9
  symmetric P35 L15 P37
  symmetric P36 L15 P38
  dimension "d314" distance P9 P10 = 10
  dimension "d315" distance P8 P9 = 6
  dimension "d316" distance P14 P15 = 10
  dimension "d317" distance P13 P14 = 6
  dimension "d344" diameter C2 = 0.6
  dimension "d345" diameter C3 = 0.6
  dimension "d346" diameter C4 = 1.9
  dimension "d347" diameter C5 = 1.9
  dimension "d348" = -1
  dimension "d349" = -1
extrude "Extrude7" cut sketch "Sketch38" profile of L1 L2 L3 L4 L7 L8 L9 L10 C2 C3 C4 C5 C6 A3 C7 A4 C8 C9 C10 C11 against normal blind 4.4
extrude "Extrude11" cut sketch "Sketch38" profile of C2 C3 C4 C5 C6 A3 C7 A4 C8 C9 C10 C11 L17 L19 L20 L21 L22 L23 L24 against normal blind 6.4 (magnitude of "-( 2 mm + 4.4 mm )")
work_plane "WorkPlane1" AlongDistance 0
sketch "Sketch45" plane through (0, -56, 0) normal (0, -1, 0) x axis (-1, 0, 0)
  circle C1 centre (-5, 0) radius 3.6
  circle C2 centre (5, 0) radius 3.6
  dimension "d407" diameter C1 = 7.2
  dimension "d408" diameter C2 = 7.2
extrude "Extrude58" cut sketch "Sketch45" against normal blind 30
delete_face "DeleteFace1"
delete_face "DeleteFace2"
chamfer "Chamfer8" distance 1
extrude "Extrude59" cut of existing geometry blind -50
component_insert "Component Insert23"
as_built_joint "As-built12"
chamfer "Chamfer9" distance 1
position "Position23"
extrude "Extrude60" cut of existing geometry blind 50
extrude "Extrude61" cut of existing geometry blind 48
extrude "Extrude62" cut of existing geometry blind 47
extrude "Extrude63" cut of existing geometry blind 50
offset_faces "OffsetFaces25"
offset_faces "OffsetFaces26" distance -0.3
chamfer "Chamfer3" distance 3.2
fillet "Fillet13" radius 1
extrude "Extrude12" new body sketch "Sketch38" profile of L1 L2 L3 L4 L7 L8 L9 L10 C4 C5 C6 A3 C7 A4 C9 C11 L18 L17 L19 L20 L21 L22 L23 L24 against normal blind 3
combine "Combine3"
combine "Combine4"
sketch "Sketch11" plane through (0, 0, 0) normal (0, 0, -1) x axis (1, 0, 0)
  line L1 (14.9993, -3) -> (22.9993, -3)
  line L2 (13.9993, 2) -> (13.9993, -2)
  line L3 (22.9993, 3) -> (14.9993, 3)
  line L4 (23.9993, -2) -> (23.9993, 2)
  line L5 (-22.9993, -3) -> (-14.9993, -3)
  line L6 (-23.9993, 2) -> (-23.9993, -2)
  line L7 (-14.9993, 3) -> (-22.9993, 3)
  line L8 (-13.9993, -2) -> (-13.9993, 2)
  curve K1 (-6.3745, 8.9461) -> (-6.3901, -11.0127)
  curve K2 (9.9484, -7.9462) -> (2.6969, 10.6486)
  line L9 (24.1493, -2) -> (24.1493, 2)
  line L10 (22.9993, 3.15) -> (14.9993, 3.15)
  line L11 (13.8493, 2) -> (13.8493, -2)
  line L12 (14.9993, -3.15) -> (22.9993, -3.15)
  line L13 (-14.9993, 3.15) -> (-22.9993, 3.15)
  line L14 (-24.1493, 2) -> (-24.1493, -2)
  line L15 (-22.9993, -3.15) -> (-14.9993, -3.15)
  line L16 (-13.8493, -2) -> (-13.8493, 2)
  arc A1 centre (14.9993, -2) radius 1 clockwise from (14.9993, -3) to (13.9993, -2)
  arc A2 centre (14.9993, 2) radius 1 clockwise from (13.9993, 2) to (14.9993, 3)
  arc A3 centre (22.9993, 2) radius 1 clockwise from (22.9993, 3) to (23.9993, 2)
  arc A4 centre (22.9993, -2) radius 1 clockwise from (23.9993, -2) to (22.9993, -3)
  arc A5 centre (-22.9993, -2) radius 1 clockwise from (-22.9993, -3) to (-23.9993, -2)
  arc A6 centre (-22.9993, 2) radius 1 clockwise from (-23.9993, 2) to (-22.9993, 3)
  arc A7 centre (-14.9993, 2) radius 1 clockwise from (-14.9993, 3) to (-13.9993, 2)
  arc A8 centre (-14.9993, -2) radius 1 clockwise from (-13.9993, -2) to (-14.9993, -3)
  circle C1 centre (0, 0) radius 27
  arc A9 centre (0, 0) radius 12.7324 clockwise from (9.9484, -7.9462) to (-6.3901, -11.0127)
  arc A10 centre (0, 0) radius 10.9848 clockwise from (-6.3745, 8.9461) to (2.6969, 10.6486)
  arc A11 centre (22.9993, -2) radius 1.15 clockwise from (24.1493, -2) to (22.9993, -3.15)
  arc A12 centre (22.9993, 2) radius 1.15 clockwise from (22.9993, 3.15) to (24.1493, 2)
  arc A13 centre (14.9993, 2) radius 1.15 clockwise from (13.8493, 2) to (14.9993, 3.15)
  arc A14 centre (14.9993, -2) radius 1.15 clockwise from (14.9993, -3.15) to (13.8493, -2)
  arc A15 centre (-14.9993, 2) radius 1.15 clockwise from (-14.9993, 3.15) to (-13.8493, 2)
  arc A16 centre (-22.9993, 2) radius 1.15 clockwise from (-24.1493, 2) to (-22.9993, 3.15)
  arc A17 centre (-22.9993, -2) radius 1.15 clockwise from (-22.9993, -3.15) to (-24.1493, -2)
  arc A18 centre (-14.9993, -2) radius 1.15 clockwise from (-13.8493, -2) to (-14.9993, -3.15)
  circle C2 centre (-20.95, 0) radius 0.3
  circle C3 centre (-17.05, 0) radius 0.3
  circle C4 centre (20.95, 0) radius 0.3
  circle C5 centre (17.05, 0) radius 0.3
  dimension "d357" = -0.15
  dimension "d358" = -0.15
extrude "Extrude13" cut sketch "Sketch11" profile of L1 A1 L2 A2 L3 A3 L4 A4 L5 A5 L6 A6 L7 A7 L8 A8 L12 L11 L9 A11 A12 L10 A13 A14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 along a picked direction to an object
component_insert "Component Insert1"
as_built_joint "As-built1"
position "Position22"
work_plane "WorkPlane2" RotateAngle 0
sketch "Sketch12" plane through (0, -0.4556, 0) normal (0, -1, 0) x axis (-1, 0, 0)
  line L1 (-7, 157) -> (0, 157)
  line L2 (-7, 167.5) -> (-7, 157)
  line L3 (0, 167.5) -> (-7, 167.5)
  line L4 (0, 157) -> (0, 167.5)
  line L5 (-4.3, 158.4) -> (-2.1, 158.4)
  line L6 (-4.3, 160.1) -> (-4.3, 158.4)
  line L7 (-2.1, 160.1) -> (-4.3, 160.1)
  line L8 (-2.1, 158.4) -> (-2.1, 160.1)
  line L9 (-4.3, 161.6) -> (-2.1, 161.6)
  line L10 (-4.3, 163.4) -> (-4.3, 161.6)
  line L11 (-2.1, 163.4) -> (-4.3, 163.4)
  line L12 (-2.1, 161.6) -> (-2.1, 163.4)
  line L13 (-4.3, 164.8) -> (-2.1, 164.8)
  line L14 (-4.3, 166.7) -> (-4.3, 164.8)
  line L15 (-2.1, 166.7) -> (-4.3, 166.7)
  line L16 (-2.1, 164.8) -> (-2.1, 166.7)
  horizontal L1
  vertical L2
  horizontal L3
  vertical L4
  horizontal L5
  vertical L6
  horizontal L7
  vertical L8
  horizontal L9
  vertical L10
  horizontal L11
  vertical L12
  horizontal L13
  vertical L14
  horizontal L15
  vertical L16
extrude "Extrude1" new body sketch "Sketch12" along a picked direction blind -16
offset_faces "OffsetFaces1" distance -3
move "Move1"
